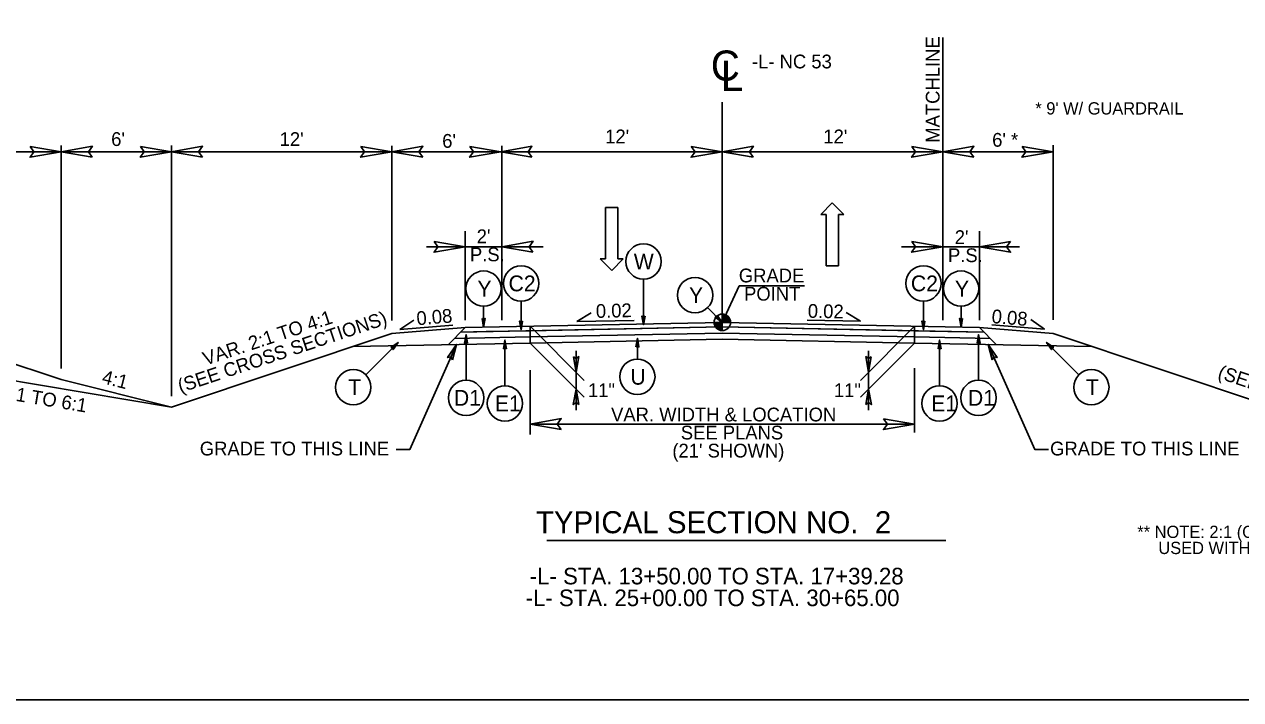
# Model space of a CAD drawing. Extents: x 1548135 to 1549339, y 868664 to 869085.
# Drawn here: x 1548182.7 to 1548249, y 868939.3 to 868976.1 of the extents above; entities that cross this region are included whole.
import ezdxf

# ---------------------------------------------------------------- set-up
doc = ezdxf.new("R2010")
doc.units = 0
for name, color, linetype in [('Default', 7, 'Continuous'), ('P_RDY_TC_Pvmt_Asphalt_Base_Course', 7, 'Continuous'), ('Prop Dimension Text', 7, 'Continuous'), ('Prop Terminator CELL', 7, 'Continuous'), ('Sheet_Data_Field_CELL', 7, 'Continuous'), ('Sheet_Plan', 7, 'Continuous'), ('Sheet_Title_Block_Text', 7, 'Continuous'), ('Typical Curb CELL', 7, 'Continuous'), ('Typical Grade Point Symbol CELL', 7, 'Continuous'), ('Typical Hinge Slope Arterial CELL', 7, 'Continuous'), ('Typical Hinge Slope Interstate CELL', 7, 'Continuous'), ('Typical Pavement Slope CELL', 7, 'Continuous'), ('Typical Pavement Slope Information CELL', 7, 'Continuous'), ('Typical Shoulder Slope CELL', 7, 'Continuous'), ('Typical Shoulder Slope Information CELL', 7, 'Continuous'), ('Typical Terminator CELL', 7, 'Continuous'), ('Typical Text Centerline CELL', 7, 'Continuous'), ('Typical Text General CELL', 7, 'Continuous'), ('Typical Text Grade Point CELL', 7, 'Continuous'), ('z - Construction', 7, 'Continuous')]:
    doc.layers.add(name, color=color, linetype=linetype)

msp = doc.modelspace()

# ---------------------------------------------------------------- linework, layer by layer
at = {"layer": 'Default'}
msp.add_lwpolyline([(1548135.738, 869049.324), (1548305.738, 869049.324), (1548305.738, 868939.324), (1548135.738, 868939.324)], close=True, dxfattribs=at)
at = {"layer": 'P_RDY_TC_Pvmt_Asphalt_Base_Course'}
for points in [[(1548183.052, 868969.447), (1548184.739, 868969.157), (1548183.043, 868968.857), (1548183.258, 868969.157)], [(1548186.427, 868968.866), (1548184.739, 868969.157), (1548186.436, 868969.457), (1548186.221, 868969.157)], [(1548189.052, 868969.447), (1548190.739, 868969.157), (1548189.043, 868968.857), (1548189.258, 868969.157)], [(1548192.427, 868968.866), (1548190.739, 868969.157), (1548192.436, 868969.457), (1548192.221, 868969.157)], [(1548201.05, 868969.447), (1548202.738, 868969.157), (1548201.041, 868968.857), (1548201.256, 868969.157)], [(1548204.425, 868968.866), (1548202.738, 868969.157), (1548204.434, 868969.457), (1548204.219, 868969.157)], [(1548206.991, 868969.447), (1548208.678, 868969.157), (1548206.981, 868968.857), (1548207.197, 868969.157)], [(1548210.366, 868968.866), (1548208.678, 868969.157), (1548210.375, 868969.457), (1548210.159, 868969.157)], [(1548219.05, 868969.447), (1548220.738, 868969.157), (1548219.041, 868968.857), (1548219.256, 868969.157)], [(1548222.425, 868968.866), (1548220.738, 868969.157), (1548222.434, 868969.457), (1548222.219, 868969.157)], [(1548231.05, 868969.447), (1548232.738, 868969.157), (1548231.041, 868968.857), (1548231.256, 868969.157)], [(1548234.425, 868968.866), (1548232.738, 868969.157), (1548234.434, 868969.457), (1548234.219, 868969.157)], [(1548237.061, 868969.447), (1548238.749, 868969.157), (1548237.052, 868968.857), (1548237.268, 868969.157)], [(1548205.05, 868964.274), (1548206.738, 868963.984), (1548205.041, 868963.684), (1548205.256, 868963.984)], [(1548210.425, 868963.693), (1548208.738, 868963.984), (1548210.434, 868964.284), (1548210.219, 868963.984)], [(1548231.05, 868964.274), (1548232.738, 868963.984), (1548231.041, 868963.684), (1548231.256, 868963.984)], [(1548236.425, 868964.274), (1548234.738, 868963.984), (1548236.435, 868963.684), (1548236.219, 868963.984)], [(1548211.957, 868954.039), (1548210.269, 868954.329), (1548211.966, 868954.629), (1548211.751, 868954.329)], [(1548229.52, 868954.624), (1548231.208, 868954.334), (1548229.511, 868954.034), (1548229.726, 868954.334)]]:
    msp.add_lwpolyline(points, close=True, dxfattribs=at)
at = {"layer": 'Prop Dimension Text'}
for p, q in [((1548206.487, 868959.335), (1548220.738, 868959.62)), ((1548220.738, 868959.62), (1548234.988, 868959.335))]:
    msp.add_line(p, q, dxfattribs=at)
at = {"layer": 'Prop Terminator CELL'}
msp.add_lwpolyline([(1548206.738, 868959.59), (1548220.738, 868959.87), (1548234.738, 868959.59), (1548234.988, 868959.335), (1548232.038, 868959.394), (1548232.038, 868959.394), (1548220.738, 868959.62), (1548210.269, 868959.411), (1548210.274, 868959.411), (1548207.871, 868959.363), (1548206.487, 868959.335)], close=True, dxfattribs=at)
at = {"layer": 'Sheet_Data_Field_CELL'}
for p, q in [((1548155.89, 868966.373), (1548184.738, 868956.757)), ((1548202.738, 868959.257), (1548190.738, 868955.257)), ((1548238.749, 868959.256), (1548267.597, 868949.64)), ((1548174.739, 868957.923), (1548190.738, 868955.257)), ((1548184.738, 868956.757), (1548190.738, 868955.257))]:
    msp.add_line(p, q, dxfattribs=at)
at = {"layer": 'Sheet_Plan'}
for p, q in [((1548202.738, 868959.257), (1548206.738, 868959.59)), ((1548238.749, 868959.256), (1548234.738, 868959.59))]:
    msp.add_line(p, q, dxfattribs=at)
at = {"layer": 'Typical Curb CELL'}
for p, q in [((1548220.29, 868959.87), (1548220.738, 868959.87)), ((1548220.737, 868959.423), (1548220.738, 868959.87)), ((1548220.738, 868959.87), (1548220.737, 868959.423)), ((1548220.738, 868959.87), (1548220.738, 868960.318)), ((1548221.185, 868959.87), (1548220.738, 868959.87))]:
    msp.add_line(p, q, dxfattribs=at)
for points in [[(1548220.292, 868959.87), (1548220.292, 868959.821)], [(1548220.301, 868959.87), (1548220.301, 868959.769)], [(1548220.31, 868959.87), (1548220.31, 868959.737)], [(1548220.319, 868959.87), (1548220.319, 868959.71)], [(1548220.328, 868959.87), (1548220.328, 868959.689)], [(1548220.337, 868959.87), (1548220.337, 868959.67)], [(1548220.346, 868959.87), (1548220.346, 868959.653)], [(1548220.355, 868959.87), (1548220.355, 868959.637)], [(1548220.364, 868959.87), (1548220.364, 868959.624)], [(1548220.373, 868959.87), (1548220.373, 868959.611)], [(1548220.382, 868959.87), (1548220.382, 868959.599)], [(1548220.39, 868959.87), (1548220.39, 868959.588)], [(1548220.399, 868959.87), (1548220.399, 868959.577)], [(1548220.408, 868959.87), (1548220.408, 868959.567)], [(1548220.417, 868959.87), (1548220.417, 868959.557)], [(1548220.426, 868959.87), (1548220.426, 868959.548)], [(1548220.435, 868959.87), (1548220.435, 868959.54)], [(1548220.444, 868959.87), (1548220.444, 868959.532)], [(1548220.453, 868959.87), (1548220.453, 868959.524)], [(1548220.462, 868959.87), (1548220.462, 868959.517)], [(1548220.471, 868959.87), (1548220.471, 868959.51)], [(1548220.48, 868959.87), (1548220.48, 868959.504)], [(1548220.489, 868959.87), (1548220.489, 868959.498)], [(1548220.498, 868959.87), (1548220.498, 868959.492)], [(1548220.507, 868959.87), (1548220.507, 868959.486)], [(1548220.516, 868959.87), (1548220.516, 868959.481)], [(1548220.525, 868959.87), (1548220.525, 868959.476)], [(1548220.534, 868959.87), (1548220.534, 868959.471)], [(1548220.543, 868959.87), (1548220.543, 868959.467)], [(1548220.552, 868959.87), (1548220.552, 868959.463)], [(1548220.561, 868959.87), (1548220.561, 868959.459)], [(1548220.569, 868959.87), (1548220.569, 868959.455)], [(1548220.578, 868959.87), (1548220.578, 868959.451)], [(1548220.587, 868959.87), (1548220.587, 868959.448)], [(1548220.596, 868959.87), (1548220.596, 868959.446)], [(1548220.605, 868959.87), (1548220.605, 868959.442)], [(1548220.614, 868959.87), (1548220.614, 868959.441)], [(1548220.623, 868959.87), (1548220.623, 868959.438)], [(1548220.632, 868959.87), (1548220.632, 868959.436)], [(1548220.641, 868959.87), (1548220.641, 868959.434)], [(1548220.65, 868959.87), (1548220.65, 868959.432)], [(1548220.659, 868959.87), (1548220.659, 868959.43)], [(1548220.668, 868959.87), (1548220.668, 868959.429)], [(1548220.677, 868959.87), (1548220.677, 868959.427)], [(1548220.686, 868959.87), (1548220.686, 868959.426)], [(1548220.695, 868959.87), (1548220.695, 868959.425)], [(1548220.704, 868959.87), (1548220.704, 868959.424)], [(1548220.713, 868959.87), (1548220.713, 868959.424)], [(1548220.722, 868959.87), (1548220.722, 868959.423)], [(1548220.731, 868959.87), (1548220.731, 868959.423), (1548220.731, 868959.423)], [(1548220.742, 868960.318), (1548220.742, 868960.318), (1548220.742, 868959.87)], [(1548220.751, 868960.318), (1548220.751, 868959.87)], [(1548220.759, 868960.317), (1548220.759, 868959.87)], [(1548220.768, 868960.317), (1548220.768, 868959.87)], [(1548220.777, 868960.316), (1548220.777, 868959.87)], [(1548220.786, 868960.315), (1548220.786, 868959.87)], [(1548220.795, 868960.314), (1548220.795, 868959.87)], [(1548220.804, 868960.313), (1548220.804, 868959.87)], [(1548220.813, 868960.312), (1548220.813, 868959.87)], [(1548220.822, 868960.31), (1548220.822, 868959.87)], [(1548220.831, 868960.308), (1548220.831, 868959.87)], [(1548220.84, 868960.306), (1548220.84, 868959.87)], [(1548220.849, 868960.304), (1548220.849, 868959.87)], [(1548220.858, 868960.301), (1548220.858, 868959.87)], [(1548220.867, 868960.299), (1548220.867, 868959.87)], [(1548220.876, 868960.296), (1548220.876, 868959.87)], [(1548220.885, 868960.293), (1548220.885, 868959.87)], [(1548220.894, 868960.29), (1548220.894, 868959.87)], [(1548220.903, 868960.286), (1548220.903, 868959.87)], [(1548220.912, 868960.282), (1548220.912, 868959.87)], [(1548220.921, 868960.278), (1548220.921, 868959.87)], [(1548220.93, 868960.274), (1548220.93, 868959.87)], [(1548220.939, 868960.27), (1548220.939, 868959.87)], [(1548220.947, 868960.265), (1548220.947, 868959.87)], [(1548220.956, 868960.26), (1548220.956, 868959.87)], [(1548220.965, 868960.255), (1548220.965, 868959.87)], [(1548220.974, 868960.25), (1548220.974, 868959.87)], [(1548220.983, 868960.244), (1548220.983, 868959.87)], [(1548220.992, 868960.238), (1548220.992, 868959.87)], [(1548221.001, 868960.231), (1548221.001, 868959.87)], [(1548221.01, 868960.225), (1548221.01, 868959.87)], [(1548221.019, 868960.218), (1548221.019, 868959.87)], [(1548221.028, 868960.21), (1548221.028, 868959.87)], [(1548221.037, 868960.202), (1548221.037, 868959.87)], [(1548221.046, 868960.194), (1548221.046, 868959.87)], [(1548221.055, 868960.185), (1548221.055, 868959.87)], [(1548221.064, 868960.177), (1548221.064, 868959.87)], [(1548221.073, 868960.167), (1548221.073, 868959.87)], [(1548221.082, 868960.156), (1548221.082, 868959.87)], [(1548221.091, 868960.145), (1548221.091, 868959.87)], [(1548221.1, 868960.133), (1548221.1, 868959.87)], [(1548221.109, 868960.12), (1548221.109, 868959.87)], [(1548221.118, 868960.106), (1548221.118, 868959.87)], [(1548221.126, 868960.091), (1548221.126, 868959.87)], [(1548221.135, 868960.075), (1548221.135, 868959.87)], [(1548221.144, 868960.056), (1548221.144, 868959.87)], [(1548221.153, 868960.035), (1548221.153, 868959.87)], [(1548221.162, 868960.01), (1548221.162, 868959.87)], [(1548221.171, 868959.98), (1548221.171, 868959.87)], [(1548221.18, 868959.934), (1548221.18, 868959.87)]]:
    msp.add_lwpolyline(points, dxfattribs=at)
msp.add_circle((1548220.737, 868959.87), 0.448, dxfattribs=at)
for start, end in [(179.99048, 269.99048), (359.99048, 89.99048)]:
    msp.add_arc((1548220.737, 868959.87), 0.448, start, end, dxfattribs=at)
at = {"layer": 'Typical Grade Point Symbol CELL'}
for p, q in [((1548232.738, 868959.99), (1548232.738, 868975.387)), ((1548220.738, 868959.87), (1548220.738, 868971.863)), ((1548220.738, 868969.157), (1548174.74, 868969.157)), ((1548184.739, 868957.354), (1548184.739, 868969.502)), ((1548190.738, 868955.848), (1548190.738, 868969.502)), ((1548202.738, 868959.971), (1548202.738, 868969.482)), ((1548207.738, 868969.157), (1548205.738, 868969.157)), ((1548208.738, 868959.99), (1548208.738, 868969.482)), ((1548220.738, 868969.157), (1548238.749, 868969.157)), ((1548233.738, 868969.157), (1548235.738, 868969.157)), ((1548238.749, 868960.008), (1548238.749, 868969.52)), ((1548206.738, 868959.99), (1548206.738, 868964.834)), ((1548234.738, 868959.99), (1548234.738, 868964.834)), ((1548210.988, 868963.984), (1548204.63, 868963.984)), ((1548230.488, 868963.984), (1548236.918, 868963.984))]:
    msp.add_line(p, q, dxfattribs=at)
at = {"layer": 'Typical Hinge Slope Arterial CELL'}
msp.add_line((1548221.661, 868961.857), (1548225.218, 868961.857), dxfattribs=at)
at = {"layer": 'Typical Hinge Slope Interstate CELL'}
for p, q in [((1548216.448, 868962.221), (1548216.448, 868959.735)), ((1548209.785, 868961.029), (1548209.785, 868959.467)), ((1548231.691, 868961.029), (1548231.691, 868959.467)), ((1548207.74, 868960.745), (1548207.74, 868959.61)), ((1548219.935, 868960.672), (1548220.738, 868959.87)), ((1548233.735, 868960.745), (1548233.735, 868959.61)), ((1548204.738, 868959.424), (1548206.738, 868959.59)), ((1548206.738, 868959.59), (1548205.82, 868958.655)), ((1548206.789, 868956.72), (1548206.789, 868959.205)), ((1548210.269, 868958.744), (1548210.269, 868959.661)), ((1548213.221, 868956.709), (1548210.269, 868959.661)), ((1548210.269, 868959.077), (1548220.738, 868959.287)), ((1548210.269, 868958.744), (1548210.269, 868959.077)), ((1548220.738, 868959.287), (1548231.208, 868959.077)), ((1548228.257, 868956.71), (1548231.209, 868959.661)), ((1548231.208, 868958.744), (1548231.208, 868959.661)), ((1548231.208, 868958.744), (1548231.208, 868959.077)), ((1548234.686, 868956.72), (1548234.686, 868959.205)), ((1548201.324, 868957.017), (1548203.082, 868958.775)), ((1548208.903, 868956.418), (1548208.903, 868958.904)), ((1548210.269, 868958.744), (1548220.738, 868958.953)), ((1548213.222, 868955.792), (1548210.271, 868958.744)), ((1548216.111, 868957.869), (1548216.111, 868959.003)), ((1548220.738, 868958.953), (1548231.208, 868958.744)), ((1548228.256, 868955.793), (1548231.208, 868958.744)), ((1548232.564, 868956.418), (1548232.564, 868958.904)), ((1548240.152, 868957.017), (1548238.393, 868958.775)), ((1548212.774, 868958.311), (1548212.775, 868955.084)), ((1548228.704, 868958.311), (1548228.704, 868955.085))]:
    msp.add_line(p, q, dxfattribs=at)
for points in [[(1548207.659, 868960.079), (1548207.74, 868959.61), (1548207.823, 868960.082), (1548207.74, 868960.022)], [(1548209.865, 868959.935), (1548209.785, 868959.467), (1548209.701, 868959.938), (1548209.785, 868959.878)], [(1548216.528, 868960.204), (1548216.448, 868959.735), (1548216.364, 868960.207), (1548216.448, 868960.147)], [(1548220.463, 868960.259), (1548220.738, 868959.87), (1548220.345, 868960.145), (1548220.447, 868960.161)], [(1548231.772, 868959.935), (1548231.691, 868959.467), (1548231.608, 868959.938), (1548231.691, 868959.878)], [(1548233.816, 868960.079), (1548233.735, 868959.61), (1548233.652, 868960.082), (1548233.735, 868960.022)], [(1548206.87, 868958.737), (1548206.789, 868959.205), (1548206.706, 868958.734), (1548206.789, 868958.794)], [(1548234.605, 868958.737), (1548234.686, 868959.205), (1548234.769, 868958.734), (1548234.686, 868958.794)], [(1548202.693, 868958.5), (1548203.082, 868958.775), (1548202.807, 868958.383), (1548202.791, 868958.484)], [(1548206.053, 868957.834), (1548206.262, 868958.664), (1548205.781, 868957.949), (1548205.962, 868957.987)], [(1548208.984, 868958.435), (1548208.903, 868958.904), (1548208.82, 868958.432), (1548208.903, 868958.492)], [(1548216.03, 868958.535), (1548216.111, 868959.003), (1548216.194, 868958.532), (1548216.111, 868958.592)], [(1548232.484, 868958.435), (1548232.564, 868958.904), (1548232.648, 868958.432), (1548232.564, 868958.492)], [(1548235.423, 868957.834), (1548235.213, 868958.664), (1548235.694, 868957.949), (1548235.514, 868957.987)], [(1548238.782, 868958.5), (1548238.393, 868958.775), (1548238.668, 868958.383), (1548238.684, 868958.484)], [(1548212.629, 868958), (1548212.774, 868957.156), (1548212.924, 868958.004), (1548212.774, 868957.896)], [(1548228.849, 868958), (1548228.704, 868957.156), (1548228.554, 868958.005), (1548228.704, 868957.897)], [(1548212.92, 868955.395), (1548212.774, 868956.239), (1548212.625, 868955.39), (1548212.774, 868955.498)], [(1548228.559, 868955.396), (1548228.704, 868956.239), (1548228.854, 868955.391), (1548228.704, 868955.499)]]:
    msp.add_lwpolyline(points, close=True, dxfattribs=at)
for points in [[(1548206.262, 868958.664), (1548203.728, 868952.953), (1548202.977, 868952.953)], [(1548235.213, 868958.664), (1548237.747, 868952.953), (1548238.498, 868952.953)]]:
    msp.add_lwpolyline(points, dxfattribs=at)
for centre in [(1548216.448, 868963.183), (1548207.74, 868961.706), (1548209.785, 868961.99), (1548231.691, 868961.99), (1548233.735, 868961.706), (1548219.255, 868961.352), (1548216.111, 868956.908), (1548200.644, 868956.337), (1548240.831, 868956.337), (1548206.789, 868955.759), (1548208.903, 868955.457), (1548232.564, 868955.457), (1548234.686, 868955.759)]:
    msp.add_circle(centre, 0.962, dxfattribs=at)
at = {"layer": 'Typical Pavement Slope CELL'}
msp.add_line((1548206.738, 868959.59), (1548220.738, 868959.87), dxfattribs=at)
at = {"layer": 'Typical Pavement Slope Information CELL'}
for p, q in [((1548212.812, 868959.912), (1548213.595, 868960.386)), ((1548228.258, 868959.928), (1548227.475, 868960.401)), ((1548203.185, 868959.473), (1548203.936, 868959.994)), ((1548203.185, 868959.473), (1548206.068, 868959.713)), ((1548212.812, 868959.912), (1548215.933, 868959.975)), ((1548228.258, 868959.928), (1548225.366, 868959.986)), ((1548238.287, 868959.497), (1548235.404, 868959.737)), ((1548238.287, 868959.497), (1548237.536, 868960.019))]:
    msp.add_line(p, q, dxfattribs=at)
at = {"layer": 'Typical Shoulder Slope CELL'}
msp.add_line((1548221.661, 868961.857), (1548220.738, 868959.87), dxfattribs=at)
at = {"layer": 'Typical Shoulder Slope Information CELL'}
for p, q in [((1548226.101, 868965.74), (1548226.721, 868966.37)), ((1548226.721, 868966.37), (1548227.361, 868965.74)), ((1548214.384, 868963.326), (1548214.384, 868966.126)), ((1548214.384, 868966.126), (1548215.044, 868966.126)), ((1548215.044, 868966.126), (1548215.044, 868963.326)), ((1548226.401, 868965.74), (1548226.101, 868965.74)), ((1548226.401, 868962.94), (1548226.401, 868965.74)), ((1548227.361, 868965.74), (1548227.061, 868965.74)), ((1548227.061, 868965.74), (1548227.061, 868962.94)), ((1548214.724, 868962.696), (1548214.084, 868963.326)), ((1548214.084, 868963.326), (1548214.384, 868963.326)), ((1548215.344, 868963.326), (1548214.724, 868962.696)), ((1548215.044, 868963.326), (1548215.344, 868963.326)), ((1548227.061, 868962.94), (1548226.401, 868962.94))]:
    msp.add_line(p, q, dxfattribs=at)
at = {"layer": 'Typical Terminator CELL'}
for p, q in [((1548210.269, 868953.759), (1548210.269, 868957.262)), ((1548231.208, 868953.879), (1548231.208, 868957.382)), ((1548210.269, 868954.329), (1548231.208, 868954.329)), ((1548211.185, 868947.985), (1548232.906, 868947.985))]:
    msp.add_line(p, q, dxfattribs=at)
at = {"layer": 'Typical Text Grade Point CELL'}
for p, q in [((1548220.738, 868959.87), (1548234.738, 868959.59)), ((1548210.269, 868959.077), (1548206.153, 868958.995)), ((1548231.208, 868959.077), (1548235.322, 868958.995)), ((1548234.738, 868959.59), (1548235.656, 868958.655)), ((1548200.62, 868958.551), (1548210.269, 868958.744)), ((1548231.208, 868958.744), (1548240.864, 868958.551))]:
    msp.add_line(p, q, dxfattribs=at)

# ---------------------------------------------------------------- texts
at = {"layer": 'Sheet_Data_Field_CELL'}
for s, rotation, p in [('(SEE CROSS SECTIONS)', 18.43497, (1548191.238, 868956.019)), ('VAR. 2:1 TO 4:1', 18.43497, (1548192.601, 868957.51)), ('4:1', 345.96376, (1548186.913, 868956.564)), ('(SEE CROSS SECTIONS)', 341.56503, (1548247.665, 868956.85)), ('VAR. 3:1 TO 6:1', 350.53767, (1548178.824, 868956.165))]:
    msp.add_text(s, height=0.75, rotation=rotation, dxfattribs=at).set_placement(p)
at = {"layer": 'Sheet_Title_Block_Text'}
msp.add_text('C', height=1.64, dxfattribs=at).set_placement((1548220.11, 868973.031))
msp.add_text('L', height=1.641, rotation=359.9469, dxfattribs=at).set_placement((1548220.656, 868972.471))
at = {"layer": 'Typical Hinge Slope Arterial CELL'}
msp.add_text('  TYPICAL SECTION NO.  2', height=1.2, dxfattribs=at).set_placement((1548209.694, 868948.387))
at = {"layer": 'Typical Hinge Slope Interstate CELL'}
msp.add_text('MATCHLINE', height=0.75, rotation=90, dxfattribs=at).set_placement((1548232.568, 868969.648))
for s, height, p in [('-L- NC 53', 0.75, (1548222.353, 868973.698)), ('W', 0.861, (1548215.917, 868962.752)), ('C2', 0.8608, (1548209.099, 868961.56)), ('C2', 0.8608, (1548231.005, 868961.56)), ('Y', 0.861, (1548207.404, 868961.276)), ('Y', 0.861, (1548218.924, 868960.922)), ('Y', 0.861, (1548233.404, 868961.276)), ('U', 0.861, (1548215.736, 868956.477)), ('T', 0.861, (1548200.361, 868955.907)), ('11"', 0.75, (1548213.421, 868955.798)), ('11"', 0.75, (1548226.813, 868955.798)), ('T', 0.861, (1548240.54, 868955.907)), ('D1', 0.8608, (1548206.124, 868955.328)), ('E1', 0.8608, (1548208.354, 868955.026)), ('E1', 0.8608, (1548232.108, 868955.026)), ('D1', 0.8608, (1548234.112, 868955.328)), ('GRADE TO THIS LINE', 0.75, (1548192.287, 868952.623)), ('GRADE TO THIS LINE', 0.75, (1548238.585, 868952.623))]:
    msp.add_text(s, height=height, dxfattribs=at).set_placement(p)
at = {"layer": 'Typical Pavement Slope Information CELL'}
for rotation, p in [(1.45507, (1548213.861, 868960.107)), (358.85436, (1548225.386, 868960.12))]:
    msp.add_text('0.02', height=0.75, rotation=rotation, dxfattribs=at).set_placement(p)
at = {"layer": 'Typical Shoulder Slope CELL'}
for s, p in [("12'", (1548214.36, 868969.617)), ("12'", (1548226.237, 868969.617)), ("6'", (1548187.462, 868969.473)), ("12'", (1548196.634, 868969.473)), ("6'", (1548205.485, 868969.375)), ("6' *", (1548235.43, 868969.432)), ('GRADE', (1548221.636, 868962.046)), ('POINT', (1548221.921, 868961.052)), ('VAR. WIDTH & LOCATION', (1548214.681, 868954.476)), ('SEE PLANS', (1548218.477, 868953.493)), ("(21' SHOWN)", (1548218.018, 868952.51))]:
    msp.add_text(s, height=0.75, dxfattribs=at).set_placement(p)
at = {"layer": 'Typical Text Centerline CELL'}
for s, p in [("2'", (1548207.365, 868964.177)), ("2'", (1548233.393, 868964.133)), ('P.S.', (1548206.996, 868963.194)), ('P.S.', (1548233.024, 868963.149))]:
    msp.add_text(s, height=0.75, dxfattribs=at).set_placement(p)
at = {"layer": 'Typical Text General CELL'}
for s, height, p in [("* 9' W/ GUARDRAIL", 0.66824, (1548237.781, 868971.186)), ('** NOTE: 2:1 (OR STEEPER) SLOPES ', 0.66824, (1548243.335, 868948.129)), ('USED WITH ROCK PLATING', 0.66824, (1548244.48, 868947.253)), ('-L- STA. 13+50.00 TO STA. 17+39.28', 0.90387, (1548210.253, 868945.602)), ('-L- STA. 25+00.00 TO STA. 30+65.00', 0.90387, (1548210.029, 868944.417))]:
    msp.add_text(s, height=height, dxfattribs=at).set_placement(p)
at = {"layer": 'z - Construction'}
for rotation, p in [(4.76147, (1548204.117, 868959.707)), (355.23853, (1548235.379, 868959.835))]:
    msp.add_text('0.08', height=0.75, rotation=rotation, dxfattribs=at).set_placement(p)

doc.saveas('drawing.dxf')
